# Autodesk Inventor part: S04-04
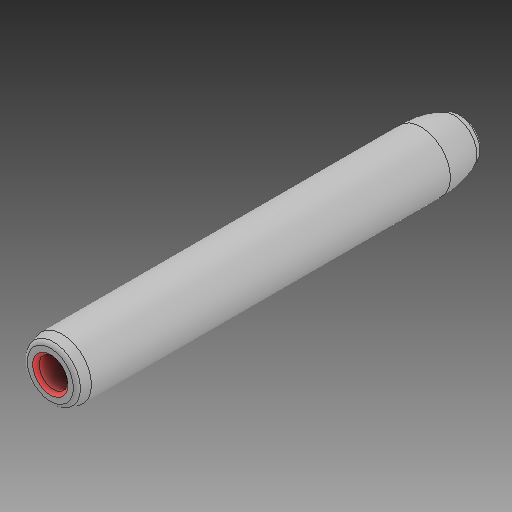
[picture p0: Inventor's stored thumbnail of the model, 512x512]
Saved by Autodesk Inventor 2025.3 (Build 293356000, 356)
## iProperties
Created: 2025-05
Part Number: S04-04
Material: Všeobecné
Document SubType Name: Modeling
Designer: Patrik
Mass: 4.92571 g
Surface Area: 26.3467 cm^2
Volume: 4.92571 cm^3
Density: 1 g/cm^3
Appearance: Výchozí
Description: Šikmý kolík bez nákružku
Stock Number: E 1034/10x70
User Status: 1.7131
Sending System: KiM GmbH
Major Version: 4.0
Minor Version: 0.0
Format Version: 0.0
Product Id: KiM GmbH
cc_prop_force_one_body: 1
Hersteller: Meusburger
Material: 1.7131 ~ 60 HRC
Bestellnummer: E 1034/10x70
Teilenummer: E 1034/10x70
Beschreibung: Schrägbolzen ohne Bund _ Inclined pin without collar
Author: Patrik
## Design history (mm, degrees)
derived "E 1034_10x70.ipt"
feature "Těleso1::E 1034_10x70.ipt" dims "d0" = 10
tag "Prvek štítků1"
node "Těleso1"
